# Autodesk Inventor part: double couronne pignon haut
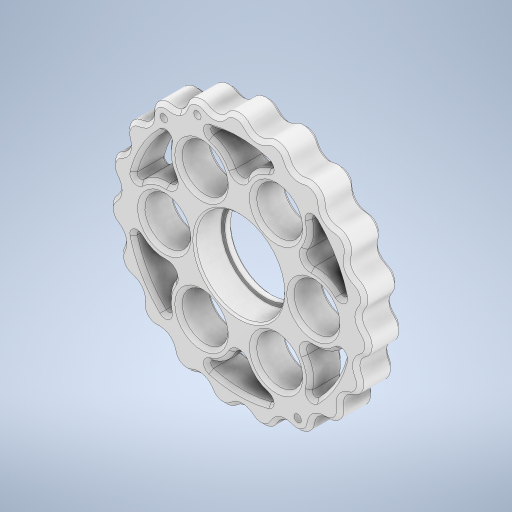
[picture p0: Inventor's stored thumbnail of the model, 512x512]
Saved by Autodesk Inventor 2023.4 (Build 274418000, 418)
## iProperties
Created: 2025-06
Part Number: double couronne pignon haut
Material: Steel
Document SubType Name: Modeling
Designer: mel
Density: 7.85 g/cm^3
Appearance: Par défaut
Author: mel
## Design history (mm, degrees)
feature "Discs Nul 0.00mm Bottom"
node "Solide1"
node "Solide2"
